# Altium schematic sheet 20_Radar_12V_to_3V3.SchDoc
size 289 x 396 mm
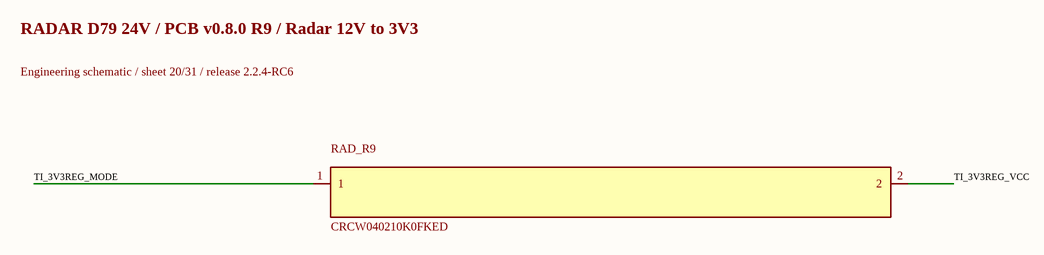
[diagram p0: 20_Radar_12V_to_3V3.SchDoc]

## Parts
RAD_R9  CRCW040210K0FKED  [0402L]

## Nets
TI_3V3REG_MODE: RAD_R9.1
TI_3V3REG_VCC: RAD_R9.2

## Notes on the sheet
- RADAR D79 24V / PCB v0.8.0 R9 / Radar 12V to 3V3
- Engineering schematic / sheet 20/31 / release 2.2.4-RC6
